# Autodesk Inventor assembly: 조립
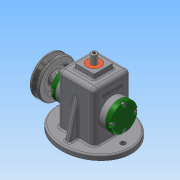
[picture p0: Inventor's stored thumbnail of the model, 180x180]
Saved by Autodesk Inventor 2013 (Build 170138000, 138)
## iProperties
Created: 2017-07
Part Number: 조립
Document SubType Name: Assembly
Designer: Administrator
Author: Administrator
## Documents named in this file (18)
- C:\Users\Administrator\Desktop\470707V1026\조립.iam
- C:\Users\Administrator\Desktop\470707V1026\본체.ipt
- C:\Users\Administrator\Desktop\470707V1026\멈춤나사 M3x8.ipt
- C:\Users\Administrator\Desktop\470707V1026\V벨트풀리.ipt
- C:\Users\Administrator\Desktop\470707V1026\고정핀 1.2 x  8.ipt
- C:\Users\Administrator\Desktop\470707V1026\뒤커버.ipt
- C:\Users\Administrator\Desktop\470707V1026\링크.ipt
- C:\Users\Administrator\Desktop\470707V1026\베어링 12 x 32 x 10.ipt
- C:\Users\Administrator\Desktop\470707V1026\볼트 M4 x 12.ipt
- C:\Users\Administrator\Desktop\470707V1026\부시.ipt
- C:\Users\Administrator\Desktop\470707V1026\슬라이드.ipt
- C:\Users\Administrator\Desktop\470707V1026\베어링 12 x 32 x 10 - 복사본.ipt
- C:\Users\Administrator\Desktop\470707V1026\볼트 M4 x 12 - 복사본.ipt
- C:\Users\Administrator\Desktop\470707V1026\앞커버.ipt
- C:\Users\Administrator\Desktop\470707V1026\오일실 12 25 7.ipt
- C:\Users\Administrator\Desktop\470707V1026\키 4 x 4 x 10.ipt
- C:\Users\Administrator\Desktop\470707V1026\편심축.ipt
- C:\Users\Administrator\Desktop\470707V1026\핀 5 x 18.ipt
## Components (3 placed, 3 different names)
1. V벨트풀리:1
2. 고정핀 1.2 x  8:1
3. 핀 5 x 18:1
